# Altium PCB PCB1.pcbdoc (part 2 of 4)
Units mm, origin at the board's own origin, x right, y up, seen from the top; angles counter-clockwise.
Board outline 96.27 x 122.17 mm, 4 copper layers (Top Layer, Inner1, Inner2, Bottom Layer); 129 components, 127 nets, 708 pads, 342 vias.
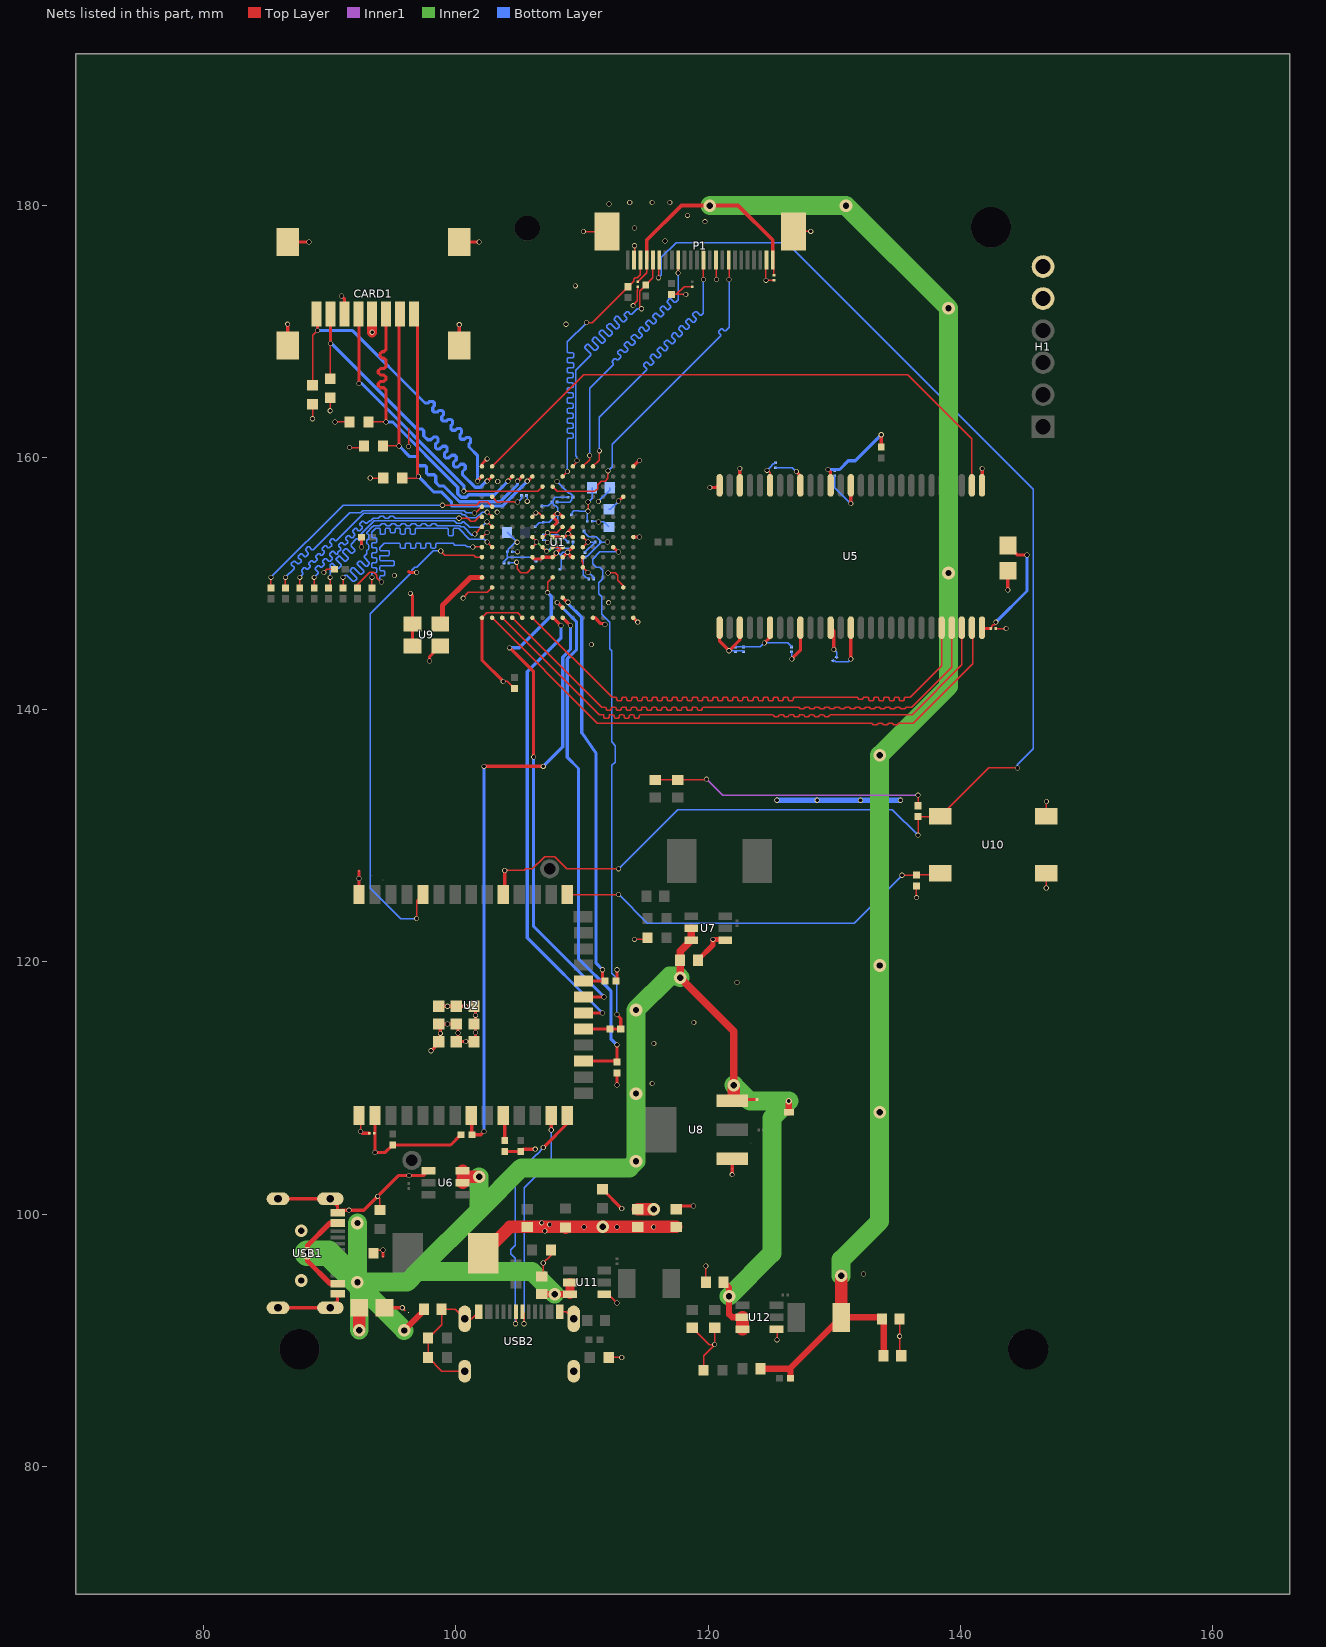
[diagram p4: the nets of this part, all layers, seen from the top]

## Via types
v1: diameter 0.4, hole 0.3, Top Layer to Bottom Layer, 308 vias
v2: diameter 1, hole 0.5, Top Layer to Bottom Layer, 33 vias
v3: diameter 0.5, hole 0.3, Top Layer to Bottom Layer, 1 vias

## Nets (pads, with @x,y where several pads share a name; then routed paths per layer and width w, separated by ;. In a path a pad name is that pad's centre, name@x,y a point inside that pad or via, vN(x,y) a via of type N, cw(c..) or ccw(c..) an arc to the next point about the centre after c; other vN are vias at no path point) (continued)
+2V8: C34.1 C70.2 C72.2 C73.2 C74.1 L4.2 P1.4 P1.24 R47.2 | length 139.5
  Top Layer w0.1: C34.1@114.427,173.931 115.135,174.639 P1.4@115.135,175.655 ; P1.24@125.136,175.652 125.222,175.566 C74.1@125.222,174.439
  Top Layer w0.3: P1.4@115.135,175.655 115.135,177.23 117.885,179.98 122.383,179.98 125.136,177.227 P1.24@125.136,175.652
  Top Layer w0.5: C70.2@124.144,87.757 126.489,87.757 ; R47.2@126.544,86.995 126.544,87.702 126.489,87.757 ; C73.2@133.793,91.694 133.666,91.821 L4.2@130.553,91.821 126.489,87.757 ; C72.2@133.92,88.773 C73.2@133.92,91.567
  Top Layer w1: L4.2@130.556,91.824 v2(130.556,95.123)
  Inner2 w1.5: v2(120.142,179.959) v2(130.937,179.959) v2(139.065,171.831) v2(139.065,150.833) 139.065,141.859 v2(133.604,136.398) v2(133.604,119.716) v2(133.604,108.091) 133.604,99.441 130.556,96.393 v2(130.556,95.123)
+3V3: C8.1 C10.1 C11.1 C12.1 C13.1 C14.1 C15.2 C16.2 C17.2 C19.2 C22.2 C23.2 C37.1 C39.1 C40.1 C45.1 C46.1 C47.1 C48.1 C50.1 C51.1 C52.1 C55.1 C56.1 C57.1 C58.1 C59.1 CARD1.4 H1.5 L1.2 R1.2 R3.1 R4.1 R5.2 R7.2 R11.2 R16.2 R17.2 R18.2 R19.2 R20.2 R21.2 R22.2 R23.1 U1.F6 U1.F7 U1.G9 U1.H6 U1.H7 U1.H11 U1.J6 U1.J7 U1.J11 U1.K11 U1.L6 U1.L11 U2.2 U5.1 U5.3 U5.9 U5.14 U5.27 U5.43 U5.49 U9.1 U9.4 | length 113.5
  Top Layer w0.1: v1(88.646,163.068) R19.2@88.646,164.22 ; v1(89.537,150.887) 89.78,151.13 R23.1@90.372,151.13 ; v1(90.043,163.703) R18.2@90.043,164.728 ; v1(90.424,162.814) R20.2@91.576,162.814 ; v1(91.567,160.782) 92.592,160.782 R17.2@92.719,160.909 ; v1(93.218,158.369) R16.2@94.243,158.369 ; v1@96.275,160.909 96.275,162.306 ; v1(104.829,151.689) 104.859,151.659 104.859,151.167 105.15,150.876 105.664,150.876 U1.L6@106.077,151.289 ; U1.J6@106.077,152.889 106.405,153.217 v1(106.405,153.288) 106.405,153.361 U1.H6@106.077,153.689 ; U1.F6@106.077,155.289 106.345,155.557 v1(106.345,155.607) 106.559,155.607 U1.F7@106.877,155.289 ; U1.J7@106.877,152.889 107.188,152.578 v1@107.188,152.527 ; U1.H7@106.877,153.689 106.926,153.689 v1(107.274,154.037) 107.484,154.037 107.519,154.071 107.835,154.071 107.881,154.025 108.013,154.025 U1.G9@108.477,154.489 ; U1.K11@110.077,152.089 110.077,151.962 109.982,151.867 109.982,151.765 110.077,151.67 U1.L11@110.077,151.289 v1(110.49,150.876) ; U1.J11@110.077,152.889 110.477,153.289 v1(110.49,153.289) 110.09,153.689 U1.H11@110.077,153.689 ; v1(124.674,158.977) 124.741,158.977 124.918,158.8 U5.49@124.918,157.788 ; C14.1@142.426,146.431 142.509,146.514 142.509,146.625 142.627,146.743 142.738,146.743 142.816,146.821 v1(142.816,146.939)
  Top Layer w0.254: U2.2@93.721,107.836 93.599,107.714 v1(93.599,104.902) 94.413,104.902 R7.2@94.996,105.485 99.591,105.485 R5.2@100.405,106.299 ; 96.271,150.952 96.346,150.876 v1(96.901,150.876) ; v1(96.393,149.225) 96.563,149.055 U9.4@96.563,146.798 U9.1@96.563,145.048 ; R21.2@103.886,104.977 R22.2@105.156,104.977 105.335,105.156 v1(106.299,105.156) ; R3.1@112.701,118.491 112.776,118.566 v1(112.776,119.38) ; v1(112.776,110.236) R4.1@112.776,111.2 ; U5.1@120.918,146.631 120.918,145.422 v1(121.666,144.674) 122.518,145.526 U5.3@122.518,146.504 ; v1(126.638,144.028) 127.318,144.707 U5.9@127.318,146.504 ; v1(129.5,159.044) 129.718,158.826 U5.43@129.718,157.788 ; v1(131.318,144.018) U5.14@131.318,146.504 ; R1.2@133.731,160.834 v1(133.731,161.798) ; U5.27@141.718,146.504 141.791,146.431 C14.1@142.426,146.431 ; C8.1@143.764,153.019 144.51,152.273 v1(145.288,152.273)
  Top Layer w0.8: v1(93.372,169.926) CARD1.4@93.372,171.374
  Top Layer w1: L1.2@102.187,96.901 104.281,98.995 C19.2@105.664,98.995 108.659,98.995 R11.2@108.712,98.942 108.765,98.995 v1(110.161,98.995) v2(111.647,98.995) v1(112.775,98.995) C23.2@114.427,98.995 v1(115.692,98.995) C22.2@117.475,98.995
  Inner2 w0.1: v1(106.405,153.288) 106.468,153.288 v1(107.188,152.568) 107.412,152.568 108.041,153.198 108.041,153.269 v1(107.274,154.037)
  Bottom Layer w0.1: C51.1@104.208,151.638 104.778,151.638 v1(104.829,151.689) ; C56.1@104.462,152.527 104.886,152.527 v1(104.894,152.519) ; C37.1@105.605,156.972 105.664,156.913 v1(105.664,156.524) ; C45.1@106.934,153.865 107.102,153.865 v1(107.274,154.037) 107.455,153.855 108.071,153.855 108.189,153.737 108.189,153.626 C46.1@108.272,153.543 108.644,153.543 C47.1@108.898,153.289 ; v1(107.188,152.568) 107.288,152.568 C57.1@107.628,152.908 ; C50.1@108.018,156.464 109.018,156.464 109.205,156.651 109.205,156.762 C39.1@109.288,156.845 109.288,156.956 109.087,157.157 108.961,157.157 v1(108.029,158.089) ; C52.1@110.236,152.468 C55.1@111.057,153.289 v1(110.49,153.289) ; v1(110.49,150.876) 110.686,150.68 110.738,150.68 110.939,150.479 C48.1@110.939,150.368 ; C40.1@110.812,154.94 111.274,154.94 v1(111.323,154.89) 111.745,154.89 C59.1@112.141,154.494 ; v1(111.301,156.512) 112.206,157.417 C58.1@112.206,157.607 ; v1(121.666,144.674) 121.974,144.674 121.98,144.668 122.726,144.668 C11.1@122.809,144.585 ; v1(124.674,158.977) 125.037,159.34 125.037,159.379 125.155,159.497 125.266,159.497 C16.2@125.349,159.58 ; C12.1@126.619,144.585 126.638,144.566 v1(126.638,144.028) ; C13.1@129.91,143.88 130.028,143.88 130.106,143.802 131.102,143.802 v1(131.318,144.018)
  Bottom Layer w0.254: v1(129.5,159.044) 130.427,159.044 131.12,159.737 131.67,159.737 v1(133.731,161.798) ; v1(142.816,146.939) 145.288,149.411 v1(145.288,152.273)
  Bottom Layer w0.4: v1(125.476,132.821) v1(128.651,132.821) v1(132.08,132.821) v1(135.255,132.821)
  other v1: 107.061,98.679 107.442,99.187 106.807,99.314 95.123,150.636 96.241,160.876
+5V: C20.2 C26.2 C30.1 C31.2 C33.2 C66.2 C71.2 U6.2 U6.3 U7.2 U7.3 U8.3 U11.2 U11.3 U12.2 U12.3 USB1.A4B9 USB1.B4A9 | length 137.8
  Top Layer w0.254: U8.3@122.301,109.093 C30.1@123.884,109.093
  Top Layer w0.4: USB1.B4A9@90.627,94.501 90.03,94.501 88.227,96.304 88.227,97.508 90.02,99.301 USB1.A4B9@90.627,99.301
  Top Layer w0.5: v2(95.904,90.786) 97.471,92.353 C20.2@97.471,92.456 ; C66.2@106.807,93.661 v2(107.842,93.661) 109.042,93.661 U11.3@109.066,93.637 ; C71.2@121.223,94.615 121.666,94.172 v2(121.666,93.492) 121.666,92.075 121.92,91.821 U12.2@122.729,91.821 ; C31.2@126.402,108.077 v3(126.402,108.966)
  Top Layer w0.6: U7.2@118.665,122.682 U7.3@118.665,121.732 117.791,120.858 C26.2@117.791,120.142 v2(117.791,118.745) 122.047,114.489 v2(122.047,110.236)
  Top Layer w0.7: U11.3@109.066,93.637 U11.2@109.066,94.587
  Top Layer w1: v2(92.345,90.805) C33.2@92.345,92.583 ; U6.2@100.537,102.491 100.537,102.97 ; U6.3@100.537,103.439 100.537,102.97 ; v2(101.854,102.97) 100.537,102.97 ; U8.3@121.914,109.009 122.047,109.142 v2(122.047,110.236) ; U12.3@122.729,90.871 U12.2@122.729,91.819
  Inner2 w1.5: v2(92.202,99.301) v2(92.202,94.615) 96.139,94.615 96.987,95.463 ; v2(92.345,90.805) 92.345,94.091 92.202,94.234 92.456,94.234 v2(95.904,90.786) ; v2(101.854,102.97) 101.854,100.33 ; v2(107.842,93.661) 106.04,95.463 96.987,95.463 ; v2(117.791,118.745) 117.664,118.872 116.964,118.872 v2(114.286,116.194) v2(114.286,109.562) v2(114.286,104.198) 113.761,103.673 105.197,103.673 101.854,100.33 ; v2(121.666,93.492) 125.062,96.888 125.062,107.626 v3(126.402,108.966) 123.317,108.966 v2(122.047,110.236) ; 96.987,95.463 101.854,100.33
  Inner2 w2: v2(88.213,96.901) 89.916,96.901 v2(92.202,94.615)
  other v2: 87.757,94.742 87.757,98.679
CCLK: R6.1 R6.2 U1.J14 U2.19 | length 44.6
  Top Layer w0.254: U2.19@110.241,114.681 R6.1@112.216,114.681 R6.2@113.082,114.681 113.082,115.518 v1(112.776,115.824) ; U1.J14@112.477,152.889 112.86,152.506 v1(112.903,152.506)
  Bottom Layer w0.1: v1(112.776,115.824) 112.776,118.703 112.374,119.105 112.374,135.577 112.649,135.852 112.649,137.16 112.395,137.414 112.374,137.414 112.374,144.674 112.222,144.826 112.222,146.928 111.564,147.586 111.564,148.951 111.335,149.18 111.335,150.07 111.654,150.389 111.654,151.043 111.419,151.278 111.133,151.278 110.848,151.562 110.848,151.93 111.424,152.506 v1(112.903,152.506)
CRYSTAL: U1.M1 U9.3 | length 5.6
  Top Layer w0.4: U9.3@98.763,146.798 98.933,146.968 98.933,148.256 101.162,150.485 101.209,150.485 101.213,150.489 U1.M1@102.077,150.489
D0: R26.1 U1.E2 | length 21
  Top Layer w0.1: R26.1@85.344,149.658 v1(85.344,150.495) ; v1@98.933,156.21 101.658,156.21 101.919,156.471 102.495,156.471 U1.E2@102.877,156.089
  Bottom Layer w0.1: v1(85.344,150.495) 91.059,156.21 v1(98.943,156.21)
D1: R27.1 U1.E1 | length 21.1
  Top Layer w0.1: R27.1@86.487,149.658 v1(86.487,150.495) ; v1(101.473,155.604) 101.592,155.604 U1.E1@102.077,156.089
  Bottom Layer w0.1: v1(86.487,150.495) 87.172,151.18 87.172,151.28 86.955,151.498 86.955,151.598 87.137,151.78 87.237,151.78 87.455,151.563 87.555,151.563 87.738,151.746 87.738,151.846 87.52,152.063 87.52,152.163 87.703,152.346 87.803,152.346 88.021,152.129 88.121,152.129 88.303,152.311 88.303,152.411 88.086,152.629 88.086,152.729 88.269,152.912 88.369,152.912 88.586,152.694 88.686,152.694 91.596,155.604 92.456,155.604 92.634,155.782 100.666,155.782 100.844,155.604 v1(101.473,155.604)
D2: R28.1 U1.F2 | length 21
  Top Layer w0.1: R28.1@87.63,149.658 v1(87.63,150.495) ; v1(102.486,155.659) 102.507,155.659 U1.F2@102.877,155.289
  Bottom Layer w0.1: v1(87.63,150.495) 87.884,150.749 87.884,150.849 87.78,150.953 87.78,151.053 87.963,151.236 88.063,151.236 88.167,151.132 88.267,151.132 88.45,151.315 88.45,151.415 88.346,151.519 88.346,151.619 88.529,151.802 88.629,151.802 88.733,151.698 88.833,151.698 89.015,151.88 89.015,151.98 88.911,152.084 88.911,152.184 89.094,152.367 89.194,152.367 89.298,152.263 89.398,152.263 89.581,152.446 89.581,152.546 89.427,152.7 89.427,152.8 89.61,152.983 89.71,152.983 89.864,152.829 89.964,152.829 90.147,153.012 90.147,153.112 89.993,153.266 89.993,153.366 90.176,153.549 90.276,153.549 90.43,153.395 90.53,153.395 92.717,155.582 100.414,155.582 100.524,155.473 100.692,155.473 100.963,155.202 101.64,155.202 102.096,155.659 v1(102.486,155.659)
D3: R29.1 U1.F1 | length 21
  Top Layer w0.1: R29.1@88.773,149.658 v1(88.773,150.495) ; v1(100.248,155.18) 100.947,155.18 101.179,154.948 101.513,154.948 101.871,155.306 102.06,155.306 U1.F1@102.077,155.289
  Bottom Layer w0.1: v1(88.773,150.495) 89.092,150.814 89.092,150.914 88.875,151.132 88.875,151.232 89.058,151.415 89.158,151.415 89.277,151.295 89.377,151.295 89.56,151.478 89.56,151.578 89.44,151.697 89.44,151.797 89.623,151.98 89.723,151.98 89.941,151.763 90.041,151.763 90.224,151.946 90.224,152.046 90.006,152.263 90.006,152.363 90.189,152.546 90.289,152.546 90.507,152.329 90.607,152.329 90.659,152.381 90.659,152.477 90.871,152.69 90.871,152.79 90.702,152.959 90.702,153.059 90.885,153.242 90.985,153.242 91.154,153.072 91.254,153.072 91.437,153.255 91.437,153.355 91.268,153.525 91.268,153.625 91.45,153.807 91.55,153.807 91.72,153.638 91.82,153.638 92.003,153.821 92.003,153.921 91.833,154.09 91.833,154.19 92.016,154.373 92.116,154.373 92.285,154.204 92.385,154.204 92.568,154.387 92.568,154.487 92.399,154.656 92.399,154.756 92.582,154.939 92.682,154.939 92.851,154.769 92.951,154.769 93.16,154.978 93.256,154.978 93.458,155.18 93.853,155.18 93.924,155.251 93.924,155.277 93.995,155.348 94.253,155.348 94.324,155.277 94.324,155.251 94.395,155.18 94.653,155.18 94.724,155.251 94.724,155.277 94.795,155.348 95.053,155.348 95.124,155.277 95.124,155.251 95.195,155.18 v1(100.248,155.18)
D4: R30.1 U1.G2 | length 21
  Top Layer w0.1: R30.1@89.916,149.658 90.043,149.785 v1(90.043,150.495) ; v1(102.471,154.892) 102.474,154.892 U1.G2@102.877,154.489
  Bottom Layer w0.1: v1(90.043,150.495) 90.043,151.482 90.189,151.628 90.207,151.628 90.619,151.216 90.719,151.216 90.902,151.399 90.902,151.499 90.49,151.911 90.49,151.929 90.755,152.194 90.773,152.194 91.185,151.782 91.285,151.782 91.468,151.965 91.468,152.065 91.056,152.477 91.056,152.577 91.239,152.76 91.339,152.76 91.701,152.398 91.801,152.398 91.983,152.581 91.983,152.681 91.694,152.97 91.694,153.133 92.12,153.559 92.22,153.559 92.388,153.391 92.488,153.391 92.671,153.573 92.671,153.673 92.503,153.842 92.503,153.942 93.541,154.98 99.879,154.98 100.081,154.778 100.414,154.778 100.541,154.905 100.65,154.905 101.102,154.453 102.031,154.453 v1(102.471,154.892)
D5: R31.1 U1.G1 | length 21
  Top Layer w0.1: R31.1@91.059,149.658 v1(91.059,150.495) ; v1(101.507,153.924) 101.512,153.924 U1.G1@102.077,154.489
  Bottom Layer w0.1: v1(91.059,150.495) 91.238,150.674 91.338,150.674 91.847,150.165 91.947,150.165 92.13,150.348 92.13,150.448 91.621,150.957 91.621,151.057 91.803,151.239 91.903,151.239 92.413,150.73 92.513,150.73 92.695,150.913 92.695,151.013 92.186,151.522 92.186,151.622 92.35,151.786 92.45,151.786 92.862,151.374 92.962,151.374 93.145,151.556 93.145,151.656 92.733,152.069 92.733,152.169 92.933,152.369 92.933,152.627 93.004,152.697 93.045,152.697 93.116,152.768 93.116,153.027 93.045,153.097 93.004,153.097 92.933,153.168 92.933,153.427 93.004,153.497 93.045,153.497 93.116,153.568 93.116,153.827 93.045,153.897 93.004,153.897 92.933,153.968 92.933,154.042 93.379,154.488 93.401,154.488 93.491,154.578 93.976,154.578 94.047,154.649 94.047,154.68 94.118,154.751 94.376,154.751 94.447,154.68 94.447,154.649 94.518,154.578 94.776,154.578 94.847,154.649 94.847,154.68 94.918,154.751 95.176,154.751 95.247,154.68 95.247,154.649 95.318,154.578 95.576,154.578 95.647,154.649 95.647,154.68 95.718,154.751 95.976,154.751 96.047,154.68 96.047,154.649 96.118,154.578 96.376,154.578 96.447,154.649 96.447,154.68 96.518,154.751 96.776,154.751 96.847,154.68 96.847,154.649 96.918,154.578 97.176,154.578 97.247,154.649 97.247,154.68 97.318,154.751 97.576,154.751 97.647,154.68 97.647,154.649 97.718,154.578 97.976,154.578 98.047,154.649 98.047,154.68 98.118,154.751 98.376,154.751 98.447,154.68 98.447,154.649 98.518,154.578 100.302,154.578 100.392,154.488 100.621,154.488 101.275,153.834 101.417,153.834 v1(101.507,153.924)
D6: R32.1 U1.J1 | length 20.9
  Top Layer w0.1: R32.1@92.202,149.658 92.202,149.921 93.178,150.897 93.512,150.897 93.747,150.662 93.747,150.474 v1(94.107,150.114) ; v1(101.346,152.908) 102.058,152.908 U1.J1@102.077,152.889
  Bottom Layer w0.1: v1(94.107,150.114) 93.959,150.262 93.959,150.546 94.03,150.617 94.294,150.617 94.365,150.687 94.365,150.946 94.294,151.017 94.03,151.017 93.959,151.087 93.959,151.346 94.03,151.417 95.052,151.417 95.123,151.487 95.123,151.746 95.052,151.817 94.03,151.817 93.959,151.887 93.959,152.146 94.03,152.217 94.671,152.217 94.742,152.287 94.742,152.546 94.671,152.617 94.03,152.617 93.959,152.687 93.959,152.821 94.321,153.183 95.539,153.183 95.61,153.112 95.61,152.852 95.68,152.781 95.939,152.781 96.01,152.852 96.01,153.112 96.08,153.183 96.339,153.183 96.41,153.112 96.41,152.852 96.48,152.781 96.739,152.781 96.81,152.852 96.81,153.112 96.88,153.183 97.139,153.183 97.21,153.112 97.21,152.852 97.28,152.781 97.539,152.781 97.61,152.852 97.61,153.112 97.68,153.183 97.939,153.183 98.01,153.112 98.01,152.852 98.08,152.781 98.339,152.781 98.41,152.852 98.41,153.112 98.48,153.183 99.801,153.183 99.928,153.056 100.751,153.056 100.899,152.908 v1(101.346,152.908)
D7: R34.1 U1.J2 | length 21
  Top Layer w0.1: R34.1@93.345,149.658 v1(93.345,150.495) ; v1(102.489,153.289) 102.489,153.277 U1.J2@102.877,152.889
  Bottom Layer w0.1: v1(93.345,150.495) 93.345,150.769 93.416,150.84 93.659,150.84 93.73,150.911 93.73,151.169 93.659,151.24 93.416,151.24 93.345,151.311 93.345,151.569 93.416,151.64 93.659,151.64 93.73,151.711 93.73,151.969 93.659,152.04 93.416,152.04 93.345,152.111 93.345,152.369 93.416,152.44 93.659,152.44 93.73,152.511 93.73,152.769 93.659,152.84 93.416,152.84 93.345,152.911 93.345,153.169 93.416,153.24 93.659,153.24 93.73,153.311 93.73,153.569 93.659,153.64 93.416,153.64 93.345,153.711 93.345,154.051 93.672,154.378 93.921,154.378 93.991,154.307 93.991,153.969 94.062,153.898 94.321,153.898 94.391,153.969 94.391,154.307 94.462,154.378 94.721,154.378 94.791,154.307 94.791,154.11 94.862,154.04 95.121,154.04 95.191,154.11 95.191,154.307 95.262,154.378 95.521,154.378 95.591,154.307 95.591,153.969 95.662,153.898 95.921,153.898 95.991,153.969 95.991,154.307 96.062,154.378 96.321,154.378 96.391,154.307 96.391,153.969 96.462,153.898 96.721,153.898 96.791,153.969 96.791,154.307 96.862,154.378 99.316,154.378 99.386,154.307 99.386,153.868 99.457,153.797 99.716,153.797 99.786,153.868 99.786,154.307 99.857,154.378 100.22,154.378 101.076,153.522 102.256,153.522 v1(102.489,153.289)
DIN: U1.T8 U2.20 | length 36.6
  Top Layer w0.254: U1.T8@107.677,147.289 107.727,147.289 v1(108.331,146.685) ; U2.20@110.241,115.951 v1(111.633,115.951)
  Bottom Layer w0.254: v1(108.331,146.685) 108.331,145.669 105.664,143.002 105.664,121.92 v1(111.633,115.951)
DN: U2.13 USB2.A7 | length 18.5
  Top Layer w0.1: USB2.A7@105.279,92.278 105.41,92.147 v1(105.41,91.313)
  Top Layer w0.254: v1(107.569,106.68) 107.569,107.714 U2.13@107.691,107.836
  Bottom Layer w0.1: v1(105.41,91.313) 105.41,102.108 107.569,104.267 v1(107.569,106.68)
DONE: pad.55@110.617,137.16 R3.2 U1.P9 U2.22 | length 33.3
  Top Layer w0.254: U1.P9@108.477,148.889 108.847,148.519 v1(108.895,148.519) ; U2.22@110.241,118.491 R3.2@111.835,118.491 111.633,118.693 v1(111.633,119.38)
  Bottom Layer w0.254: v1(108.895,148.519) 108.895,148.407 109.982,147.32 109.982,138.176 111.125,136.525 111.125,119.888 v1(111.633,119.38)
DOUT: U1.M8 U2.21 | length 40
  Top Layer w0.1: v1(107.277,149.274) 107.277,150.089 U1.M8@107.677,150.489
  Top Layer w0.254: v1(104.267,144.907) 106.172,143.002 v1(106.172,136.242) ; U2.21@110.241,117.221 v1(111.76,117.221)
  Bottom Layer w0.254: v1(104.267,144.907) 105.029,144.907 107.561,147.439 107.561,148.99 v1(107.277,149.274) ; v1(106.172,136.242) 106.172,122.809 v1(111.76,117.221)
DP: U2.14 USB2.A6 | length 19.6
  Top Layer w0.1: v1@104.779,91.313 USB2.A6@104.779,92.278
  Top Layer w0.254: v1(106.934,105.283) 108.961,107.31 U2.14@108.961,107.836
  Bottom Layer w0.1: v1(104.731,91.313) 104.731,96.503 104.373,96.861 104.373,97.195 104.731,97.553 104.731,103.08 106.405,104.754 106.466,104.754 106.701,104.989 106.701,105.05 v1(106.934,105.283)
FSCL: P1.5 R39.1 U1.A10 | length 27
  Top Layer w0.1: U1.A10@109.277,159.289 109.601,159.613 v1(109.601,159.766) ; v1(114.724,171.788) 114.59,171.922 114.59,173.162 115.062,173.634 R39.1@115.062,173.661 115.634,174.233 P1.5@115.634,175.655
  Bottom Layer w0.1: v1(109.601,159.766) 109.601,160.052 109.52,160.132 109.52,166.923 110.709,168.112 110.709,168.212 110.237,168.684 110.237,168.784 110.42,168.967 110.52,168.967 110.992,168.495 111.092,168.495 111.275,168.678 111.275,168.778 110.803,169.25 110.803,169.35 110.986,169.533 111.086,169.533 111.558,169.061 111.658,169.061 111.841,169.244 111.841,169.344 111.369,169.816 111.369,169.916 111.552,170.099 111.652,170.099 112.124,169.626 112.224,169.626 112.407,169.809 112.407,169.909 111.984,170.331 111.984,170.431 112.167,170.614 112.267,170.614 112.689,170.192 112.789,170.192 112.972,170.375 112.972,170.475 112.55,170.897 112.55,170.997 112.733,171.18 112.833,171.18 113.255,170.758 113.355,170.758 113.561,170.963 113.561,171.063 113.371,171.253 113.371,171.353 113.554,171.536 113.654,171.536 113.844,171.346 113.944,171.346 114.385,171.788 v1(114.724,171.788)
FSDA: P1.3 R38.1 U1.B9 | length 27
  Top Layer w0.1: U1.B9@108.477,158.489 108.839,158.851 v1(108.839,158.877) ; v1(110.363,170.688) 110.819,170.688 R38.1@113.665,173.534 114.115,173.984 114.115,174.12 114.233,174.238 114.369,174.238 114.634,174.503 P1.3@114.634,175.655
  Bottom Layer w0.1: v1(108.839,158.877) 108.839,161.431 108.91,161.502 109.226,161.502 109.297,161.573 109.297,161.831 109.226,161.902 108.91,161.902 108.839,161.973 108.839,162.242 108.91,162.313 109.226,162.313 109.297,162.383 109.297,162.642 109.226,162.713 108.91,162.713 108.839,162.783 108.839,163.042 108.91,163.113 109.226,163.113 109.297,163.183 109.297,163.442 109.226,163.513 108.91,163.513 108.839,163.583 108.839,163.842 108.91,163.913 109.226,163.913 109.297,163.983 109.297,164.242 109.226,164.313 108.91,164.313 108.839,164.383 108.839,164.642 108.91,164.713 109.226,164.713 109.297,164.783 109.297,165.042 109.226,165.113 108.91,165.113 108.839,165.183 108.839,165.442 108.91,165.513 109.226,165.513 109.297,165.583 109.297,165.842 109.226,165.913 108.91,165.913 108.839,165.983 108.839,166.242 108.91,166.313 109.226,166.313 109.297,166.383 109.297,166.642 109.226,166.713 108.91,166.713 108.839,166.783 108.839,167.042 108.91,167.113 109.276,167.113 109.347,167.183 109.347,167.442 109.276,167.513 108.91,167.513 108.839,167.583 108.839,167.842 108.91,167.913 109.276,167.913 109.347,167.983 109.347,168.242 109.276,168.313 108.91,168.313 108.839,168.383 108.839,169.164 v1(110.363,170.688)
GND: C8.2 C10.2 C11.2 C12.2 C13.2 C14.2 C15.1 C16.1 C17.1 C20.1 C22.1 C23.1 C26.1 C27.1 C28.1 C33.1 C34.2 C35.2 C37.2 C39.2 C40.2 C41.2 C42.2 C43.2 C44.2 C45.2 C46.2 C47.2 C48.2 C49.2 C50.2 C51.2 C52.2 C53.2 C54.2 C55.2 C56.2 C57.2 C58.2 C59.2 C61.2 C62.2 C63.2 C66.1 C67.1 C68.1 C71.1 C72.1 C73.1 C74.2 CARD1.6 CARD1.9 CARD1.10 CARD1.11 CARD1.12 H1.6 P1.2 P1.15 P1.23 P1.25 P1.26 pad.55@92.324,127.195 pad.55@94.234,96.647 pad.55@96.266,92.202 pad.55@121.914,103.597 R9.1 R10.1 R12.1 R14.1 R24.1 R25.1 R35.2 R36.2 R37.2 R40.1 R42.2 R43.2 R45.1 R46.1 U1.A1 U1.A16 U1.D2 U1.D15 U1.F8 U1.F9 U1.G8 U1.G10 U1.H1 U1.H8 U1.H9 U1.H10 U1.H16 U1.J8 U1.J9 U1.J10 U1.K6 U1.K7 U1.K8 U1.K9 U1.K10 U1.N2 U1.N15 U1.T1 U1.T5 U1.T12 U1.T16 U2.1 U2.40 U2.41 U5.6 U5.12 U5.28 U5.41 U5.46 U5.52 U5.54 U6.4 U7.4 U8.1 U9.2 U10.2 U10.4 U11.4 U12.4 USB1.1 USB1.2 USB1.3 USB1.4 USB1.A1B12 USB1.B1A12 USB2.1 USB2.2 USB2.3 USB2.4 USB2.A1B12 USB2.B1A12 | length 211
  Top Layer w0.1: U2.1@92.324,107.836 92.451,107.709 v1(92.451,106.553) ; R10.1@93.463,96.901 93.717,97.155 v1(94.234,97.155) ; v1(93.804,101.415) 93.98,101.239 R9.1@93.98,100.321 ; v1(95.758,92.583) 96.012,92.329 ; v1(100.584,148.844) 100.584,148.886 101.005,149.307 102.495,149.307 U1.N2@102.877,149.689 ; USB2.3@100.709,87.554 98.891,87.554 R42.2@97.799,88.646 R43.2@97.799,90.17 98.871,91.242 C20.1@98.871,92.456 99.956,92.456 USB2.1@100.709,91.703 101.254,91.703 USB2.A1B12@101.829,92.278 ; U1.T1@102.077,147.289 102.459,147.671 104.895,147.671 U1.T5@105.277,147.289 ; 102.235,153.797 102.477,154.039 v1(102.477,154.051) ; U1.D2@102.877,156.889 103.302,156.464 103.512,156.464 103.519,156.471 104.635,156.471 104.642,156.464 v1@104.902,156.464 ; v1(103.759,142.24) 104.088,142.24 R25.1@104.648,141.68 ; C66.1@106.807,95.061 106.934,95.188 v1(106.934,96.139) 107.56,96.765 R45.1@107.56,97.155 ; U1.J8@107.677,152.889 U1.J9@108.42,152.889 ; USB2.B1A12@108.229,92.278 108.774,92.278 USB2.2@109.349,91.703 ; v1(110.109,177.909) P1.26@111.979,177.909 ; v1(110.477,155.737) 110.49,155.75 v1(110.49,156.464) ; U11.4@111.766,93.637 112.103,93.637 v1(112.776,92.964) ; v1(112.077,150.841) 112.216,150.841 112.246,150.871 112.635,150.871 112.859,150.647 112.859,150.258 113.277,149.84 U1.N15@113.277,149.689 ; R40.1@112.132,88.646 v1(113.157,88.646) ; v1(114.063,172.035) 114.063,172.102 114.39,172.429 114.39,173.245 114.427,173.282 C34.2@114.427,173.541 ; P1.2@114.135,175.655 114.173,175.694 v1(114.173,176.784) ; v1(114.173,121.793) 115.071,121.793 R14.1@115.198,121.92 ; C27.1@115.824,134.431 C28.1@117.602,134.431 119.826,134.431 v1(119.888,134.493) ; R35.2@117.094,172.922 117.491,172.922 ; v1(118.237,172.922) 117.491,172.922 ; C68.1@118.745,90.994 120.077,89.662 v1(120.523,89.662) ; C35.2@118.745,173.541 118.11,173.541 117.491,172.922 ; R46.1@119.643,87.63 119.643,88.782 v1(120.523,89.662) ; C71.1@119.823,94.615 v1(119.823,95.885) ; C67.1@120.523,90.994 v1(120.523,89.662) ; P1.15@120.631,175.654 120.667,175.617 120.667,174.455 120.65,174.437 v1@120.65,174.117 ; P1.23@124.636,175.652 124.587,175.603 v1(124.587,174.045) 124.591,174.049 C74.2@125.222,174.049 ; U12.4@125.429,90.871 125.476,90.824 v1(125.476,90.043) ; P1.25@126.781,177.916 128.132,177.916 v1(128.143,177.927) ; C73.1@135.193,91.694 v1(135.193,90.323) 135.193,88.9 C72.1@135.32,88.773 ; v1(136.525,125.095) R37.2@136.525,126.036 ; R36.2@136.652,132.386 v1(136.652,133.223) ; C14.2@142.816,146.431 v1(143.637,146.431) ; v1(146.812,125.857) 146.821,125.866 U10.4@146.821,127.036 ; U10.2@146.821,131.536 v1(146.821,132.715)
  Top Layer w0.254: USB1.4@85.903,92.581 USB1.2@90.052,92.581 90.627,93.156 USB1.B1A12@90.627,93.701 ; USB1.3@85.903,101.221 USB1.1@90.052,101.221 90.627,100.646 USB1.A1B12@90.627,100.101 90.848,100.321 v1(91.526,100.321) 92.71,100.321 v1(93.804,101.415) 95.447,103.058 v1(96.299,103.058) 97.161,103.058 97.171,103.068 97.466,103.068 U6.4@97.837,103.439 ; CARD1.10@86.672,168.874 v1(86.672,170.565) ; CARD1.9@86.672,177.074 v1(88.357,177.074) ; v1(90.945,172.801) 91.172,172.574 CARD1.6@91.172,171.374 ; pad.55@92.324,127.195 v1(92.324,126.623) 92.324,125.463 U2.40@92.451,125.336 ; v1(92.451,106.553) 92.578,106.426 C17.1@93.15,106.426 ; v1(92.531,152.902) R24.1@92.531,153.67 ; pad.55@94.234,96.647 v1(94.234,97.155) ; C33.1@94.345,92.583 v1(95.758,92.583) ; v1(97.917,143.861) 97.917,144.202 U9.2@98.763,145.048 ; v1(98.045,112.96) 98.771,113.686 v1(98.771,114.339) 98.771,115.086 v1(99.347,115.086) 100.171,115.086 v1(100.171,114.364) 100.171,113.686 v1(100.791,113.686) 101.571,113.686 v1(101.571,114.408) v1(101.571,115.77) 101.571,116.486 v1(100.722,116.486) U2.41@100.044,116.486 v1(99.347,116.486) U2.41@98.771,116.486 ; CARD1.11@100.272,168.874 v1(100.272,170.523) ; CARD1.12@100.272,177.074 v1(101.854,177.074) ; U1.T1@102.077,147.289 102.077,143.922 v1(103.759,142.24) ; U1.A1@102.077,159.289 102.077,159.481 v1(102.489,159.893) ; U1.K6@106.077,152.089 106.218,151.948 106.736,151.948 U1.K7@106.877,152.089 U1.K8@107.677,152.089 107.964,152.376 v1(107.964,152.432) 108.42,152.889 U1.J9@108.477,152.889 ; U1.H8@107.677,153.689 U1.H9@108.477,153.689 108.628,153.689 v1(108.896,153.957) ; U1.G8@107.677,154.489 108.029,154.841 108.029,154.937 U1.F8@107.677,155.289 107.931,155.543 v1(108.068,155.543) 108.223,155.543 U1.F9@108.477,155.289 ; U1.K9@108.477,152.089 108.856,152.468 v1(108.856,152.481) ; U1.K10@109.121,152.117 109.121,152.215 v1(108.856,152.481) ; U1.J10@109.277,152.889 109.264,152.889 v1(108.856,152.481) ; U1.H10@109.277,153.689 109.009,153.957 v1(108.896,153.957) ; U1.G10@109.277,154.489 108.896,154.108 v1(108.896,153.957) ; U1.T12@110.877,147.289 111.064,147.289 111.218,147.135 111.218,147.099 111.487,146.83 111.747,146.83 v1(111.82,146.757) ; R12.1@111.633,101.972 v1(113.157,100.448) ; v1@112.903,156.591 112.979,156.591 U1.D15@113.277,156.889 ; U1.T16@114.077,147.289 v1(114.427,146.939) ; U1.H16@114.077,153.689 v1(114.554,153.691) ; U1.A16@114.077,159.289 v1(114.554,159.766) ; C22.1@117.475,100.395 117.726,100.646 v1(118.846,100.646) ; v1(120.142,157.607) 120.61,157.607 U5.54@120.918,157.915 ; v1(121.914,103.134) pad.55@121.914,103.597 U8.1@121.914,104.409 ; U5.52@122.518,157.915 v1(122.518,159.131) ; v1(124.46,145.288) 124.918,145.746 U5.6@124.918,146.504 ; v1(127,158.877) 127.318,158.559 U5.46@127.318,157.788 ; U5.12@129.718,146.504 129.972,146.25 v1(129.972,144.78) ; v1(131.318,156.337) U5.41@131.318,157.915 ; U5.28@141.718,157.788 141.732,157.802 v1(141.732,159.131) ; v1(143.764,149.479) C8.2@143.764,151.019
  Top Layer w0.4: C26.1@119.191,120.142 120.396,121.347 v1(120.396,121.793) 121.304,121.793 U7.4@121.365,121.732
  Top Layer w1: C23.1@114.427,100.395 v2(115.689,100.395)
  Inner1 w0.1: v1(119.888,134.493) 121.158,133.223 v1(136.652,133.223)
  Bottom Layer w0.1: C51.2@103.818,151.638 103.818,151.749 104.072,152.003 ; C61.2@104.075,154.051 104.089,154.051 v1(104.864,153.276) 104.711,153.276 104.155,152.721 104.155,152.567 104.115,152.527 C56.2@104.072,152.527 104.072,152.003 ; v1(104.901,156.465) 105.215,156.779 C37.2@105.215,156.972 ; C41.2@106.299,154.5 106.612,154.813 106.875,154.813 C62.2@106.934,154.872 107.397,154.872 v1(108.068,155.543) ; C54.2@106.358,151.765 106.032,152.091 104.16,152.091 104.072,152.003 ; C63.2@106.807,156.151 107.315,156.151 C50.2@107.628,156.464 ; C45.2@106.934,153.475 107.043,153.475 v1(107.263,153.256) ; C46.2@107.882,153.543 107.935,153.49 107.935,152.991 C57.2@108.018,152.908 108.113,152.813 109.188,152.813 ; v1(107.964,152.432) 108.103,152.432 108.346,152.19 ; C42.2@108.068,154.826 v1(108.068,155.543) ; C53.2@108.263,151.13 108.346,151.213 108.346,151.919 108.446,152.019 C49.2@108.517,152.019 108.346,152.19 ; C39.2@108.898,156.845 107.898,156.845 107.711,156.658 107.711,156.547 C50.2@107.628,156.464 ; C43.2@109.152,155.448 109.235,155.531 109.235,155.642 109.353,155.76 109.731,155.76 109.754,155.737 v1(110.477,155.737) 110.422,155.682 C40.2@110.422,154.94 ; C47.2@109.288,153.289 109.288,152.913 109.188,152.813 ; C44.2@110.168,154.178 110.168,154.067 110.534,153.701 111.146,153.701 111.447,153.4 C55.2@111.447,153.289 ; v1(110.49,156.464) 110.806,156.78 C58.2@110.806,157.607 ; C48.2@110.549,150.368 110.443,150.474 110.323,150.474 110.088,150.709 110.088,151.93 C52.2@110.236,152.078 110.319,152.161 110.43,152.161 111.447,153.178 C55.2@111.447,153.289 ; v1@112.014,153.289 C55.2@111.447,153.289 ; C59.2@112.141,155.894 112.254,155.894 v1(112.903,156.544) ; C10.2@122.174,144.975 C11.2@122.809,144.975 124.147,144.975 v1(124.46,145.288) 126.306,145.288 C12.2@126.619,144.975 ; C16.1@125.349,159.19 126.687,159.19 v1(127,158.877) ; v1(129.972,144.78) 130.186,144.566 C13.2@130.186,144.156 ; C15.1@130.048,158.555 130.048,157.607 v1(131.318,156.337) ; C50.2@107.628,156.464 107.711,156.381 107.711,156.27 107.829,156.152 107.94,156.152 108.068,156.024 v1(108.068,155.543) ; 108.346,152.19 108.346,152.331 108.496,152.481 v1(108.856,152.481) 109.188,152.813
  other v1: 132.334,95.25 115.57,110.363 115.697,113.538 118.872,115.189 122.301,118.364 110.744,145.161 112.121,148.485 112.029,153.289 103.279,155.659 103.326,158.088 108.733,170.561 109.474,173.609 120.667,174.117 116.586,177.165 114.173,178.181 119.761,178.689 118.364,179.197 112.141,180.086 113.792,180.213 115.57,180.213 116.967,180.213
HREF: P1.9 U1.A11 | length 27
  Top Layer w0.1: U1.A11@110.077,159.289 110.617,159.829 v1(110.617,160.147) ; v1(117.634,174.625) P1.9@117.634,175.655
  Bottom Layer w0.1: v1(110.617,160.147) 110.617,165.481 112.485,167.349 112.485,167.449 112.395,167.54 112.395,167.64 112.578,167.823 112.678,167.823 112.768,167.732 112.868,167.732 113.079,167.943 113.079,168.043 112.848,168.274 112.848,168.374 113.031,168.557 113.131,168.557 113.362,168.326 113.462,168.326 113.645,168.509 113.645,168.609 113.364,168.89 113.364,168.99 113.547,169.173 113.647,169.173 113.928,168.892 114.028,168.892 114.211,169.075 114.211,169.175 113.93,169.456 113.93,169.556 114.113,169.739 114.213,169.739 114.494,169.458 114.594,169.458 114.776,169.64 114.776,169.74 114.495,170.021 114.495,170.121 114.678,170.304 114.778,170.304 115.059,170.023 115.159,170.023 115.342,170.206 115.342,170.306 115.061,170.587 115.061,170.687 115.244,170.87 115.344,170.87 115.625,170.589 115.725,170.589 115.908,170.772 115.908,170.872 115.627,171.153 115.627,171.253 115.81,171.436 115.91,171.436 116.191,171.155 116.291,171.155 116.474,171.338 116.474,171.438 116.193,171.719 116.193,171.819 116.375,172.001 116.475,172.001 116.756,171.72 116.856,171.72 117.039,171.903 117.039,172.003 116.758,172.284 116.758,172.384 116.941,172.567 117.041,172.567 117.322,172.286 117.422,172.286 117.634,172.498 v1(117.634,174.625)
INITN: pad.55@102.235,127.254 R5.1 U1.T9 U2.8 | length 49.2
  Top Layer w0.254: U2.8@101.341,107.836 101.271,107.766 R5.1@101.271,106.299 101.981,106.299 v1(102.235,106.553) ; v1(102.235,135.509) v1(106.934,135.509) ; U1.T9@108.477,147.289 109.081,146.685 v1(109.093,146.685)
  Bottom Layer w0.254: v1(102.235,106.553) pad.55@102.235,127.254 v1(102.235,135.509) ; v1(106.934,135.509) 108.485,137.06 108.485,144.172 109.093,144.78 v1(109.093,146.685)
M_CLK: CARD1.5 U1.C7 | length 24
  Top Layer w0.1: v1(100.639,157.325) 100.656,157.307 106.495,157.307 U1.C7@106.877,157.689
  Top Layer w0.254: CARD1.5@92.272,171.374 92.329,171.317 v1(92.329,165.862)
  Bottom Layer w0.254: v1(92.329,165.862) 92.541,165.862 100.639,157.764 v1(100.639,157.325)
M_CMD: CARD1.3 R20.1 U1.B4 | length 25.6
  Top Layer w0.1: R20.1@93.082,162.814 v1(94.472,162.814)
  Top Layer w0.254: v1(94.472,162.814) 94.472,165.339 94.293,165.518 94.033,165.518 93.853,165.698 93.853,165.847 94.033,166.026 94.293,166.026 94.472,166.206 94.472,166.355 94.293,166.534 94.033,166.534 93.853,166.714 93.853,166.863 94.033,167.042 94.293,167.042 94.472,167.222 94.472,167.699 94.293,167.878 94.16,167.878 93.98,168.058 93.98,168.207 94.16,168.386 94.293,168.386 94.472,168.566 CARD1.3@94.472,171.374 ; v1(104.14,158.115) 104.14,158.152 U1.B4@104.477,158.489
  Bottom Layer w0.254: v1(94.472,162.814) 94.98,162.814 100.16,157.634 100.16,157.126 100.44,156.846 100.837,156.846 101.036,157.045 103.07,157.045 v1(104.14,158.115)
M_D0: CARD1.7 R18.1 U1.B2 | length 26.9
  Top Layer w0.1: R18.1@90.043,166.234 90.043,169.008 v1(90.072,169.037)
  Top Layer w0.254: v1(90.072,169.037) CARD1.7@90.072,171.374 ; v1(102.489,158.115) 102.503,158.115 U1.B2@102.877,158.489
  Bottom Layer w0.254: v1(90.072,169.037) 90.128,169.037 96.902,162.263 97.304,162.263 97.462,162.104 97.462,161.703 97.766,161.398 98.02,161.398 98.232,161.61 98.486,161.61 98.591,161.505 98.591,161.251 98.38,161.039 98.38,160.785 98.485,160.68 98.739,160.68 98.95,160.892 99.204,160.892 99.31,160.786 99.31,160.532 99.098,160.321 99.098,160.067 99.203,159.961 99.457,159.961 99.669,160.173 99.923,160.173 100.028,160.068 100.028,159.814 99.816,159.602 99.816,159.348 99.922,159.243 100.176,159.243 100.387,159.455 100.641,159.455 100.747,159.349 100.747,159.095 100.535,158.884 100.535,158.63 101.529,157.636 101.925,157.636 102.404,158.115 v1(102.489,158.115)
M_D1: CARD1.8 R19.1 U1.B1 | length 28.5
  Top Layer w0.1: R19.1@88.646,165.726 88.646,169.672 v1(89.027,170.053)
  Top Layer w0.254: CARD1.8@88.972,171.374 89.027,171.319 v1(89.027,170.053) ; v1(101.727,158.115) 101.727,158.139 U1.B1@102.077,158.489
  Bottom Layer w0.254: v1(89.027,170.053) 91.821,170.053 97.558,164.316 97.812,164.316 97.939,164.443 98.193,164.443 98.298,164.338 98.298,164.084 98.171,163.957 98.171,163.703 98.277,163.597 98.531,163.597 98.658,163.724 98.912,163.724 99.017,163.619 99.017,163.365 98.89,163.238 98.89,162.984 98.995,162.879 99.249,162.879 99.376,163.006 99.63,163.006 99.735,162.901 99.735,162.647 99.608,162.52 99.608,162.266 99.714,162.16 99.968,162.16 100.095,162.287 100.349,162.287 100.454,162.182 100.454,161.928 100.327,161.801 100.327,161.547 100.432,161.442 100.686,161.442 100.813,161.569 101.067,161.569 101.172,161.464 101.172,161.21 101.045,161.083 101.045,160.829 101.727,160.147 v1(101.727,158.115)
M_D2: CARD1.1 R16.1 U1.B6 | length 25.4
  Top Layer w0.1: R16.1@95.876,158.369 96.901,158.369 v1(97.028,158.496)
  Top Layer w0.254: CARD1.1@96.672,171.374 96.957,171.089 96.957,158.567 v1(97.028,158.496) ; v1(105.664,158.115) 105.703,158.115 U1.B6@106.077,158.489
  Bottom Layer w0.254: v1(97.028,158.496) 98.269,157.255 98.895,157.255 99.653,156.497 99.653,156.138 103.687,156.138 v1(105.664,158.115)
M_D3: CARD1.2 R17.1 U1.B5 | length 25.2
  Top Layer w0.1: R17.1@94.225,160.909 v1(95.504,160.909)
  Top Layer w0.254: v1(95.504,160.909) 95.504,171.306 CARD1.2@95.572,171.374 ; v1(104.902,158.115) U1.B5@105.277,158.489
  Bottom Layer w0.254: v1(95.504,160.909) 95.517,160.909 96.362,160.064 96.857,160.064 96.969,159.952 96.969,159.457 97.081,159.346 97.575,159.346 97.687,159.234 97.687,158.739 97.799,158.627 98.294,158.627 98.406,158.515 98.406,158.021 98.692,157.734 99.051,157.734 100.294,156.492 103.54,156.492 104.902,157.854 v1(104.902,158.115)
MCLK: P1.13 U1.A12 | length 27.1
  Top Layer w0.1: U1.A12@110.877,159.289 111.379,159.791 v1(111.379,160.528) ; v1(119.634,174.117) P1.13@119.634,175.655
  Bottom Layer w0.1: v1(111.379,160.528) 111.379,163.195 115.124,166.94 115.124,167.04 114.893,167.271 114.893,167.371 115.076,167.554 115.176,167.554 115.407,167.323 115.507,167.323 115.69,167.506 115.69,167.606 115.409,167.887 115.409,167.987 115.592,168.17 115.692,168.17 115.973,167.889 116.073,167.889 116.255,168.071 116.255,168.171 115.974,168.452 115.974,168.552 116.157,168.735 116.257,168.735 116.538,168.454 116.638,168.454 116.821,168.637 116.821,168.737 116.54,169.018 116.54,169.118 116.723,169.301 116.823,169.301 117.104,169.02 117.204,169.02 117.387,169.203 117.387,169.303 117.106,169.584 117.106,169.684 117.289,169.867 117.389,169.867 117.67,169.586 117.77,169.586 117.952,169.768 117.952,169.868 117.671,170.149 117.671,170.249 117.854,170.432 117.954,170.432 118.235,170.151 118.335,170.151 118.518,170.334 118.518,170.434 118.237,170.715 118.237,170.815 118.42,170.998 118.52,170.998 118.801,170.717 118.901,170.717 119.084,170.9 119.084,171 118.803,171.281 118.803,171.381 118.986,171.564 119.086,171.564 119.367,171.283 119.467,171.283 119.634,171.45 v1(119.634,174.117)
PCLK: P1.17 U1.C8 | length 27
  Top Layer w0.1: U1.C8@107.677,157.689 108.059,157.307 111.035,157.307 111.259,157.531 111.259,157.847 111.519,158.107 111.835,158.107 112.059,158.331 112.059,158.647 112.077,158.665 v1(112.077,158.937) ; P1.17@121.634,175.656 121.666,175.624 v1(121.666,174.117)
  Bottom Layer w0.1: v1(112.077,158.937) 112.416,159.276 112.416,161.057 121.006,169.647 121.006,169.747 120.852,169.901 120.852,170.001 121.034,170.183 121.134,170.183 121.288,170.029 121.388,170.029 121.666,170.307 v1(121.666,174.117)
PROGRAM: R37.1 U2.27 U10.3 | length 32.2
  Top Layer w0.1: U2.27@108.834,125.336 112.89,125.336 v1(112.903,125.349) ; v1(135.382,126.873) 136.497,126.873 R37.1@136.525,126.901 138.287,126.901 U10.3@138.421,127.036
  Bottom Layer w0.1: v1(112.903,125.349) 115.189,123.063 131.572,123.063 v1(135.382,126.873)
PROGRAMN: pad.55@108.839,136.377 R4.2 U1.R9 U2.17 | length 42.2
  Top Layer w0.254: v1(108.04,148.5) 108.066,148.5 U1.R9@108.477,148.089 ; U2.17@110.241,112.141 112.701,112.141 R4.2@112.776,112.066 v1(112.776,113.428)
  Bottom Layer w0.254: v1(108.04,148.5) 109.572,146.968 109.572,144.758 108.839,144.025 pad.55@108.839,136.377 108.839,136.229 109.728,135.34 109.728,120.269 112.297,117.7 112.297,113.907 v1(112.776,113.428)
RESET: P1.6 R36.1 U2.31 U10.1 | length 113.1
  Top Layer w0.1: v1(103.881,127.254) 105.41,127.254 105.537,127.381 106.079,127.381 107.043,128.345 107.841,128.345 108.805,127.381 v1(112.903,127.381) ; v1(116.078,174.244) 116.078,175.599 P1.6@116.135,175.655 ; v1(136.652,130.048) R36.1@136.652,131.52 138.405,131.52 U10.1@138.421,131.536 142.267,135.382 v1(144.526,135.382)
  Top Layer w0.254: U2.31@103.881,125.336 v1(103.881,127.254)
  Bottom Layer w0.1: v1(112.903,127.381) 117.602,132.08 134.62,132.08 v1(136.652,130.048) ; v1(116.078,174.244) 116.304,174.47 116.304,175.867 117.475,177.038 126.238,177.038 145.796,157.48 145.796,136.906 144.526,135.636 v1(144.526,135.382)
RX: U1.K1 U2.36 | length 39.7
  Top Layer w0.1: v1(96.901,123.444) 96.901,124.833 U2.36@97.404,125.336 ; v1(98.807,152.582) 99.135,152.254 101.434,152.254 101.599,152.089 U1.K1@102.077,152.089
  Bottom Layer w0.1: v1(96.901,123.444) 95.631,123.444 93.218,125.857 93.218,147.598 96.499,150.879 96.499,151.043 96.734,151.278 96.898,151.278 98.202,152.582 v1(98.807,152.582)
SCL: R21.1 U2.10 | length 1.9
  Top Layer w0.254: U2.10@103.881,107.836 103.886,107.831 R21.1@103.886,105.918
SD_A0: U1.T6 U5.23 | length 46.8
  Top Layer w0.1: U1.T6@106.077,147.289 112.396,140.97 112.696,140.97 112.767,140.899 112.767,140.787 112.837,140.716 113.096,140.716 113.167,140.787 113.167,140.899 113.237,140.97 113.496,140.97 113.567,140.899 113.567,140.787 113.637,140.716 113.896,140.716 113.967,140.787 113.967,140.899 114.037,140.97 114.296,140.97 114.367,140.899 114.367,140.787 114.437,140.716 114.696,140.716 114.767,140.787 114.767,140.899 114.837,140.97 115.096,140.97 115.167,140.899 115.167,140.787 115.237,140.716 115.496,140.716 115.567,140.787 115.567,140.899 115.637,140.97 115.896,140.97 115.967,140.899 115.967,140.787 116.037,140.716 116.296,140.716 116.367,140.787 116.367,140.899 116.437,140.97 116.696,140.97 116.767,140.899 116.767,140.787 116.837,140.716 117.096,140.716 117.167,140.787 117.167,140.899 117.237,140.97 117.496,140.97 117.567,140.899 117.567,140.787 117.637,140.716 117.896,140.716 117.967,140.787 117.967,140.899 118.037,140.97 118.296,140.97 118.367,140.899 118.367,140.787 118.437,140.716 118.696,140.716 118.767,140.787 118.767,140.899 118.837,140.97 119.096,140.97 119.167,140.899 119.167,140.787 119.237,140.716 119.496,140.716 119.567,140.787 119.567,140.899 119.637,140.97 119.896,140.97 119.967,140.899 119.967,140.787 120.037,140.716 120.296,140.716 120.367,140.787 120.367,140.899 120.437,140.97 120.696,140.97 120.767,140.899 120.767,140.787 120.837,140.716 121.096,140.716 121.167,140.787 121.167,140.899 121.237,140.97 121.496,140.97 121.567,140.899 121.567,140.787 121.637,140.716 121.896,140.716 121.967,140.787 121.967,140.899 122.037,140.97 122.296,140.97 122.367,140.899 122.367,140.787 122.437,140.716 122.696,140.716 122.767,140.787 122.767,140.899 122.837,140.97 123.096,140.97 123.167,140.899 123.167,140.787 123.237,140.716 123.496,140.716 123.567,140.787 123.567,140.899 123.637,140.97 123.896,140.97 123.967,140.899 123.967,140.787 124.037,140.716 124.296,140.716 124.367,140.787 124.367,140.899 124.437,140.97 124.696,140.97 124.767,140.899 124.767,140.787 124.837,140.716 125.096,140.716 125.167,140.787 125.167,140.899 125.237,140.97 125.496,140.97 125.567,140.899 125.567,140.787 125.637,140.716 125.896,140.716 125.967,140.787 125.967,140.899 126.037,140.97 126.296,140.97 126.367,140.899 126.367,140.787 126.437,140.716 126.696,140.716 126.767,140.787 126.767,140.899 126.837,140.97 131.82,140.97 131.947,140.843 132.22,140.843 132.347,140.97 132.678,140.97 132.748,140.899 132.748,140.787 132.819,140.716 133.078,140.716 133.148,140.787 133.148,140.899 133.219,140.97 133.478,140.97 133.548,140.899 133.548,140.787 133.619,140.716 133.878,140.716 133.948,140.787 133.948,140.899 134.019,140.97 134.278,140.97 134.348,140.899 134.348,140.787 134.419,140.716 134.678,140.716 134.748,140.787 134.748,140.899 134.819,140.97 135.078,140.97 135.148,140.899 135.148,140.787 135.219,140.716 135.478,140.716 135.548,140.787 135.548,140.899 135.619,140.97 136.017,140.97 138.518,143.471 U5.23@138.518,146.504
SD_A1: U1.T4 U5.24 | length 46.8
  Top Layer w0.1: U1.T4@104.477,147.289 111.558,140.208 111.858,140.208 111.929,140.137 111.929,140.025 111.999,139.954 112.258,139.954 112.329,140.025 112.329,140.137 112.399,140.208 112.658,140.208 112.729,140.137 112.729,140.025 112.799,139.954 113.058,139.954 113.129,140.025 113.129,140.137 113.199,140.208 113.458,140.208 113.529,140.137 113.529,140.025 113.599,139.954 113.858,139.954 113.929,140.025 113.929,140.137 113.999,140.208 114.258,140.208 114.329,140.137 114.329,140.025 114.399,139.954 114.658,139.954 114.729,140.025 114.729,140.137 114.799,140.208 115.058,140.208 115.129,140.137 115.129,140.025 115.199,139.954 115.458,139.954 115.529,140.025 115.529,140.137 115.599,140.208 115.858,140.208 115.929,140.137 115.929,140.025 115.999,139.954 116.258,139.954 116.329,140.025 116.329,140.137 116.399,140.208 116.658,140.208 116.729,140.137 116.729,140.025 116.799,139.954 117.058,139.954 117.129,140.025 117.129,140.137 117.199,140.208 117.458,140.208 117.529,140.137 117.529,140.025 117.599,139.954 117.858,139.954 117.929,140.025 117.929,140.137 117.999,140.208 118.258,140.208 118.329,140.137 118.329,140.025 118.399,139.954 118.658,139.954 118.729,140.025 118.729,140.137 118.799,140.208 119.058,140.208 119.129,140.137 119.129,140.025 119.199,139.954 119.458,139.954 119.529,140.025 119.529,140.137 119.599,140.208 127.177,140.208 127.304,140.081 127.577,140.081 127.704,140.208 127.977,140.208 128.104,140.081 128.377,140.081 128.504,140.208 128.777,140.208 128.904,140.081 129.177,140.081 129.304,140.208 129.577,140.208 129.704,140.081 129.977,140.081 130.104,140.208 130.377,140.208 130.504,140.081 130.777,140.081 130.904,140.208 131.177,140.208 131.304,140.081 131.577,140.081 131.704,140.208 131.977,140.208 132.104,140.081 132.377,140.081 132.504,140.208 132.777,140.208 132.904,140.081 133.177,140.081 133.304,140.208 133.577,140.208 133.704,140.081 133.977,140.081 134.104,140.208 134.377,140.208 134.504,140.081 134.777,140.081 134.904,140.208 135.177,140.208 135.304,140.081 135.577,140.081 135.704,140.208 136.144,140.208 139.319,143.383 U5.24@139.319,146.503
SD_A2: U1.T3 U5.25 | length 46.9
  Top Layer w0.1: U1.T3@103.677,147.289 111.356,139.61 111.679,139.61 111.75,139.539 111.75,139.39 111.82,139.319 112.079,139.319 112.15,139.39 112.15,139.539 112.22,139.61 112.479,139.61 112.55,139.539 112.55,139.39 112.62,139.319 112.879,139.319 112.95,139.39 112.95,139.539 113.02,139.61 113.279,139.61 113.35,139.539 113.35,139.39 113.42,139.319 113.679,139.319 113.75,139.39 113.75,139.539 113.82,139.61 114.079,139.61 114.15,139.539 114.15,139.39 114.22,139.319 114.479,139.319 114.55,139.39 114.55,139.539 114.62,139.61 125.143,139.61 125.214,139.539 125.214,139.517 125.285,139.446 125.543,139.446 125.614,139.517 125.614,139.539 125.685,139.61 125.943,139.61 126.014,139.539 126.014,139.517 126.085,139.446 126.343,139.446 126.414,139.517 126.414,139.539 126.485,139.61 126.743,139.61 126.814,139.539 126.814,139.517 126.885,139.446 127.143,139.446 127.214,139.517 127.214,139.539 127.285,139.61 127.543,139.61 127.614,139.539 127.614,139.517 127.685,139.446 127.943,139.446 128.014,139.517 128.014,139.539 128.085,139.61 128.343,139.61 128.414,139.539 128.414,139.517 128.485,139.446 128.743,139.446 128.814,139.517 128.814,139.539 128.885,139.61 129.143,139.61 129.214,139.539 129.214,139.517 129.285,139.446 129.543,139.446 129.614,139.517 129.614,139.539 129.685,139.61 136.181,139.61 140.118,143.547 U5.25@140.118,146.504
SD_A3: U1.T2 U5.26 | length 46.7
  Top Layer w0.1: U1.T2@102.877,147.289 111.228,138.938 132.99,138.938 133.117,138.811 133.39,138.811 133.517,138.938 133.79,138.938 133.917,138.811 134.19,138.811 134.317,138.938 134.59,138.938 134.717,138.811 134.99,138.811 135.117,138.938 136.271,138.938 140.97,143.637 140.97,146.452 U5.26@140.918,146.504
SD_A4: U1.A2 U5.29 | length 46.9
  Top Layer w0.1: U1.A2@102.877,159.289 110.158,166.57 135.817,166.57 140.918,161.469 U5.29@140.918,157.788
